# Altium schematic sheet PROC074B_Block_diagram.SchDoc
size 431 x 279 mm; Date: Not shown in title block; ApprovedBy: Not shown in title block; CheckedBy: Not shown in title block; Author: Not shown in title block; CompanyName: Not shown in title block; Engineer: Not shown in title block; Organization: Not shown in title block; Address1: Not shown in title block; Address2: Not shown in title block; Address3: Not shown in title block; Address4: Not shown in title block; DocumentNumber: 1; Revision: Use project parameter SCH_Rev; SheetNumber: 1; SheetTotal: 22; PageSetup: Record=PageOptions¦CenterHorizontal=True¦CenterVertical=True¦PrintScale=1.00¦XCorrection=1.00¦YCorrection=1.00¦PrintKind=0¦BorderSize=5000000¦LeftOffset=0¦BottomOffset=0¦Orientation=2¦PaperLength=1000¦PaperWidth=1000¦Scale=100¦PaperSource=15¦PrintQuality=600¦MediaType=1¦DitherType=10¦PaperKind=Letter¦PrintScaleMode=1
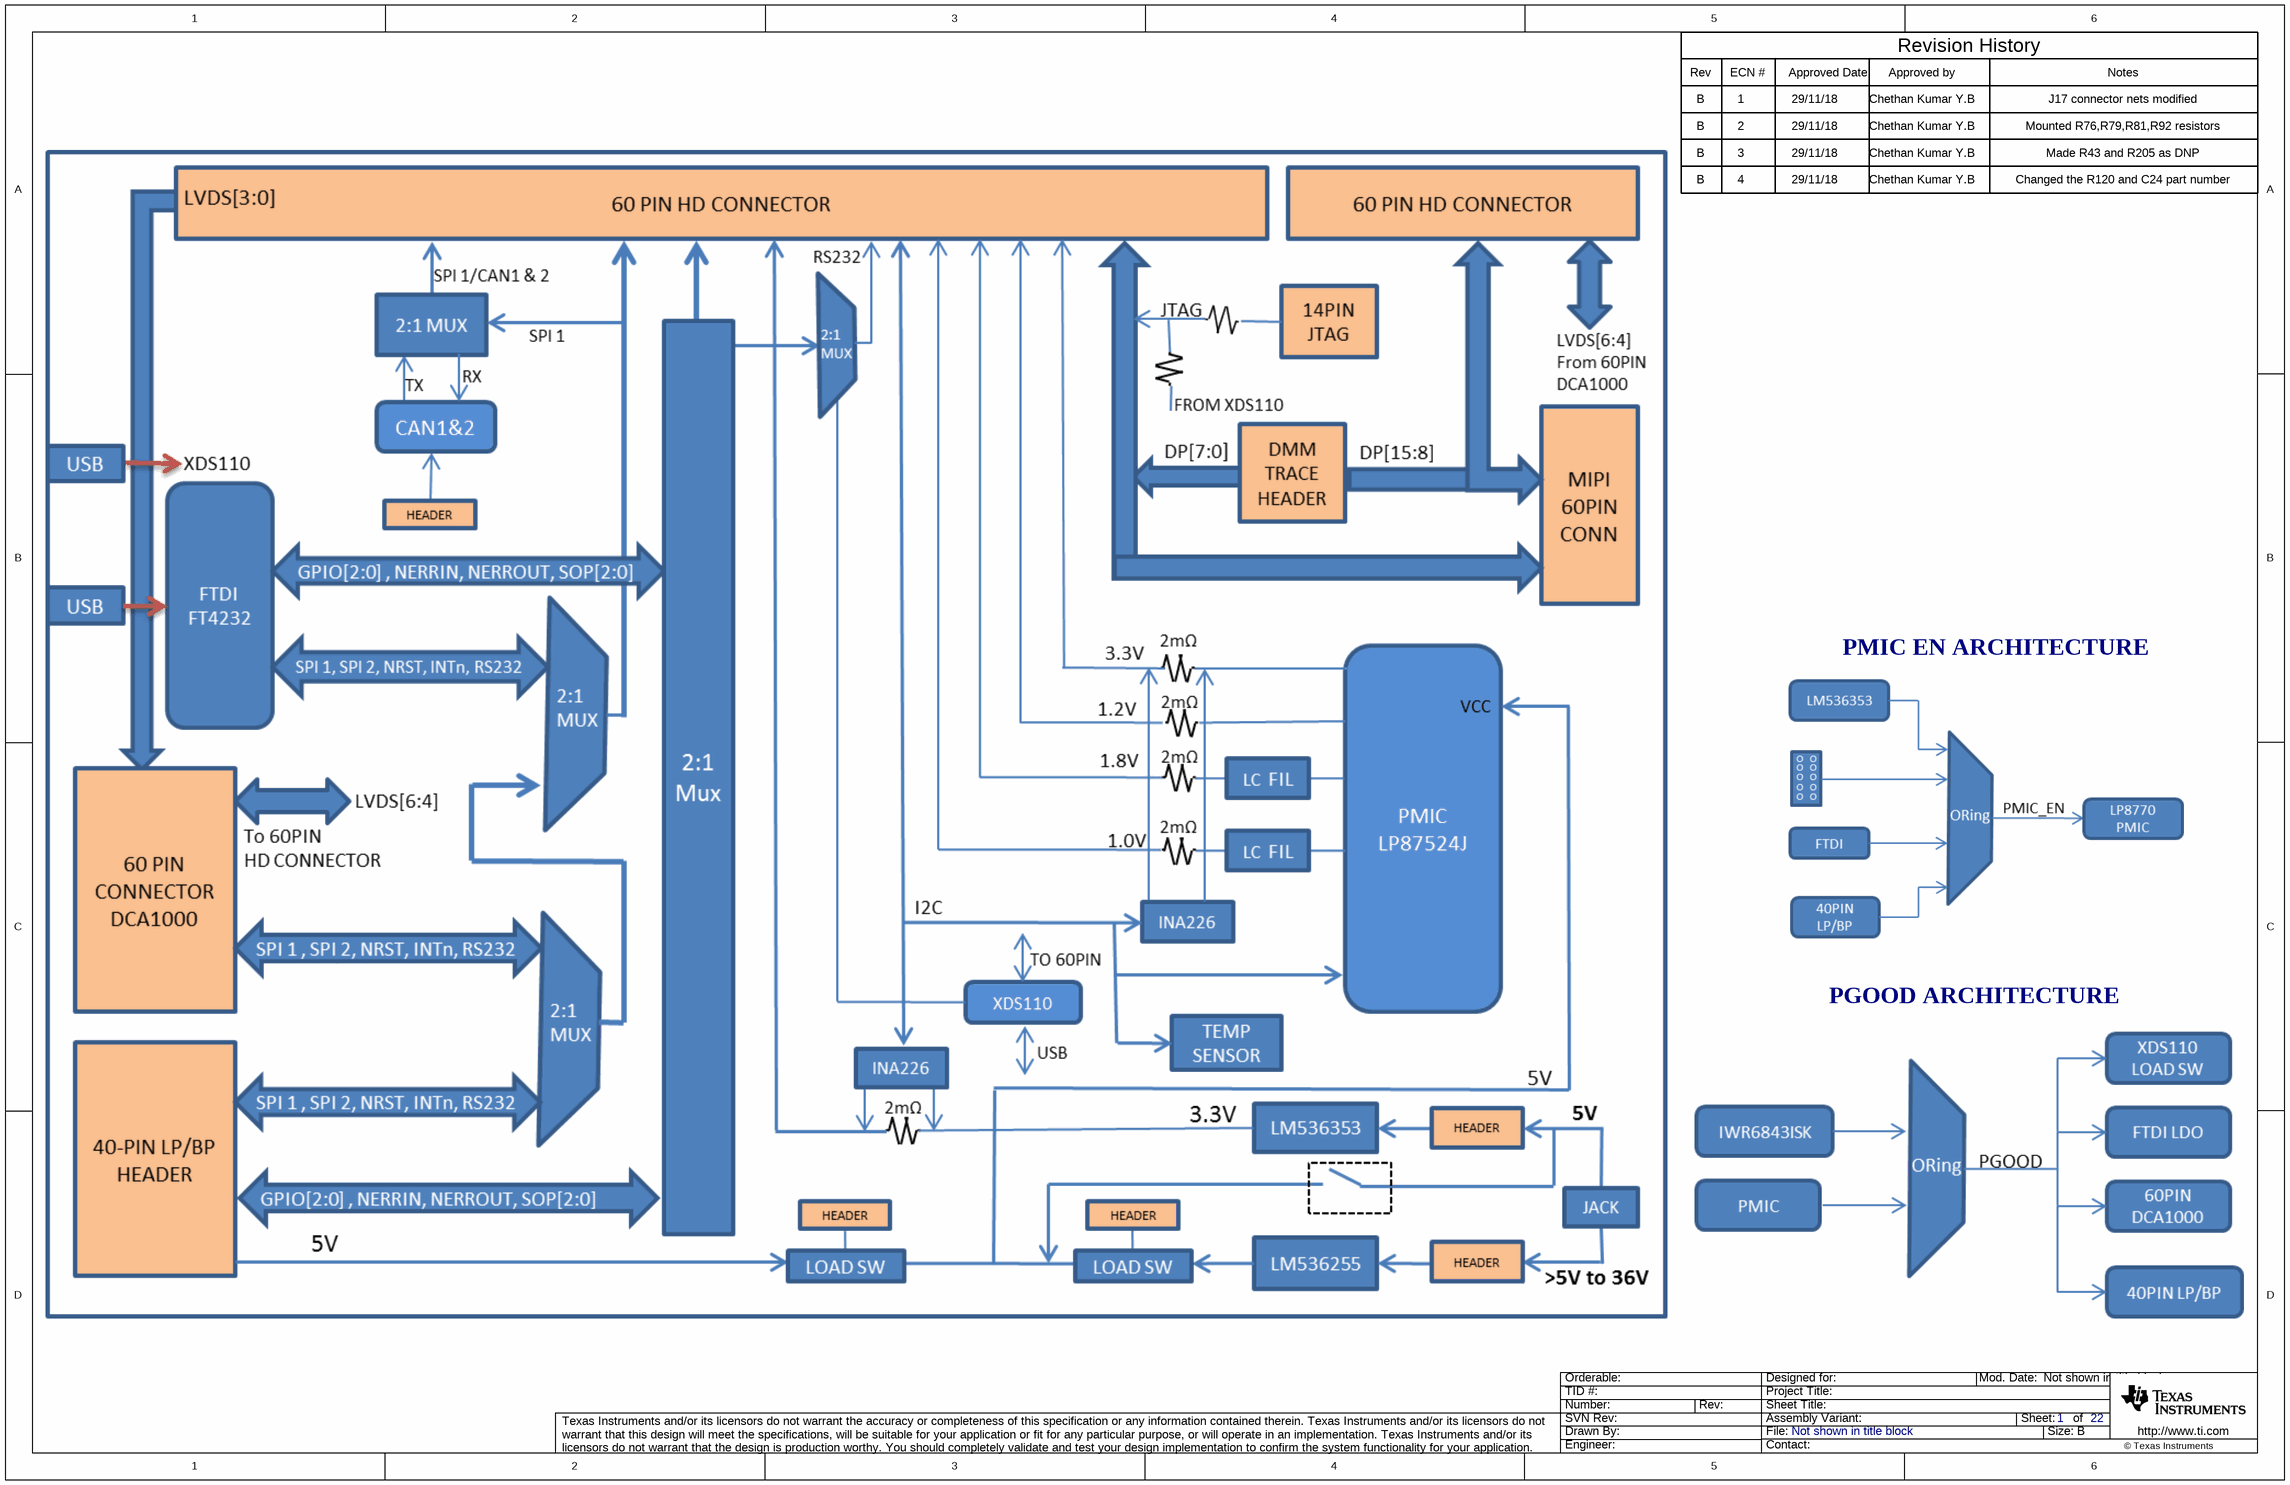
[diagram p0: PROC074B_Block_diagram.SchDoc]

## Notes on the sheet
- Rev
- B
- 1
- ECN #
- 29/11/18
- Approved Date
- Approved by
- Chethan Kumar Y.B
- Revision History
- Notes
- J17 connector nets modified
- 2
- 3
- Mounted R76,R79,R81,R92 resistors
- Made R43 and R205 as DNP
- 4
- Changed the R120 and C24 part number
- PMIC EN ARCHITECTURE
- PGOOD ARCHITECTURE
